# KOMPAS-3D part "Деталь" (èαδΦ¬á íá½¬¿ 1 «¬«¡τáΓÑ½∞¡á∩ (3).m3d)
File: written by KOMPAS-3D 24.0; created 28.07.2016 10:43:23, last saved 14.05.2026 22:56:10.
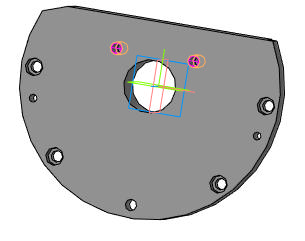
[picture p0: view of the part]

Document properties: Полное имя файла: E:\test_kompas\all_v22\Крышка балки 1 окончательная (3).m3d

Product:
- Part/product: Деталь
    Масса: 9.688835
- Part/product: Деталь  | designation 01
    Масса: 9.688835

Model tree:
1. Эскиз:1
2. Операция выдавливания:1
     Расстояние 1 = 40
3. Эскиз:2  (with: Грань.Операция выдавливания:1)
4. Элемент выдавливания:2
     Расстояние 2 = 20
5. Эскиз:13  (with: Грань.Операция выдавливания:1)
6. Элемент выдавливания:5
     Расстояние 2 = 40
7. Эскиз:14  (with: Грань.Операция выдавливания:1)
8. Эскиз:15  (with: Грань.Операция выдавливания:1, Ребро.Элемент выдавливания:2)
9. Элемент выдавливания:6
     Расстояние 2 = 40
10. Эскиз:16  (with: Грань.Операция выдавливания:1, Ребро.Элемент выдавливания:2)
11. Элемент выдавливания:7
     Расстояние 2 = 11
12. Отверстие:3  (with: Грань.Операция выдавливания:1, Ребро.Операция выдавливания:1)  (labels: M12)
     Глубина выреза = 30; Диаметр отверстия = 10.1056; Угол конуса дна = 118; Расстояние 1 = 31; Расстояние 2 = 46.4075
13. M12  (with: Грань.Отверстие:3, Грань.Операция выдавливания:1, Операция выдавливания:1)  (labels: M12; cil0_24705-2004 coarse)
     Длина резьбы = 25; Шаг резьбы = 1.75; Номинальный диаметр резьбы = 12
14. Отверстие:4  (with: Грань.Операция выдавливания:1, Ребро.Операция выдавливания:1, M12, Грань.Отверстие:4, Операция выдавливания:1)  (labels: M12; cil0_24705-2004 coarse)
     Глубина выреза = 30; Диаметр отверстия = 10.1056; Угол конуса дна = 118; Расстояние 1 = 31; Расстояние 2 = 70.8326; Длина резьбы = 25; Шаг резьбы = 1.75; Номинальный диаметр резьбы = 12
